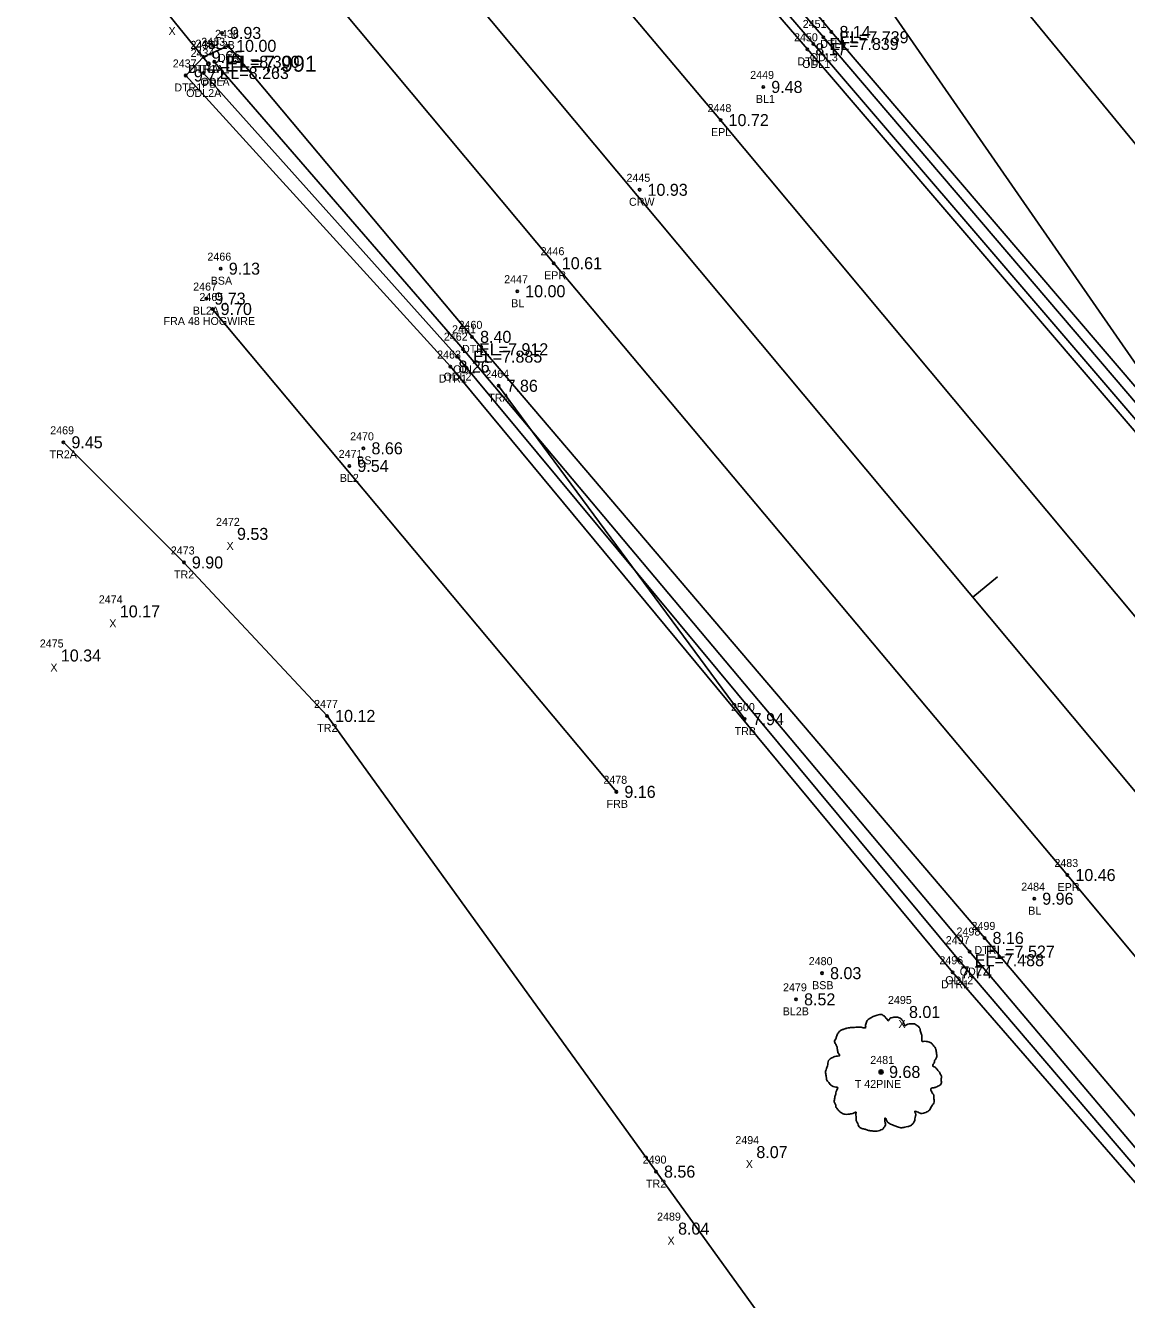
# Model space of a CAD drawing. Extents: x 2042117 to 2045853, y 303080 to 309569.
# Drawn here: x 2044504.4 to 2044642, y 304432.9 to 304592 of the extents above; entities that cross this region are included whole.
import ezdxf

# ---------------------------------------------------------------- set-up
doc = ezdxf.new("R2010")
doc.units = 0
for name, color, linetype in [('RD_DTM_BkLn_txCode', 7, 'Continuous'), ('RD_EX_DR_Pipe', 7, 'Continuous'), ('RD_EX_DR_Pipe_txCode', 7, 'Continuous'), ('RD_EX_Fence_Other', 7, 'Continuous'), ('RD_EX_Fence_Other_txCode', 7, 'Continuous'), ('RD_EX_H2O', 7, 'Continuous'), ('RD_EX_H2O_txCode', 7, 'Continuous'), ('RD_EX_Misc_txCode', 7, 'Continuous'), ('RD_EX_Road', 7, 'Continuous'), ('RD_EX_Road_txCode', 7, 'Continuous'), ('RD_EX_TX_Fence_Other_ELEV', 7, 'Continuous'), ('RD_EX_TX_H2O_ELEV', 7, 'Continuous'), ('RD_EX_TX_Misc_ELEV', 7, 'Continuous'), ('RD_EX_TX_Road_ELEV', 7, 'Continuous'), ('RD_EX_TX_VEG_ELEV', 7, 'Continuous'), ('RD_EX_VEG', 7, 'Continuous'), ('RD_EX_VEG_txCode', 7, 'Continuous'), ('RD_HC_Cl', 7, 'Continuous'), ('RD_HC_Data_Tic', 7, 'Continuous'), ('RD_HC_Survey_ELEV', 7, 'Continuous'), ('RD_HC_Survey_txCode', 7, 'Continuous'), ('RD_SMD_Locator', 7, 'Continuous'), ('RD_TX_Pipe_ElevEX', 7, 'Continuous')]:
    doc.layers.add(name, color=color, linetype=linetype)

msp = doc.modelspace()

# ---------------------------------------------------------------- linework, layer by layer
at = {"layer": 'RD_EX_DR_Pipe'}
msp.add_line((2044518.06, 304598.7), (2044527.29, 304587.27), dxfattribs=at)
at = {"layer": 'RD_EX_Fence_Other'}
msp.add_line((2044527.81, 304556.63), (2044578.26, 304496.32), dxfattribs=at)
msp.add_lwpolyline([(2044487.63, 304762.15), (2044554.33, 304682.4), (2044620.57, 304604.64), (2044681.6, 304530.46), (2044725.33, 304478.72)], dxfattribs=at)
at = {"layer": 'RD_EX_H2O'}
for points in [[(2044415.25, 304826.5), (2044425.66, 304808.25), (2044476.98, 304747.65), (2044539.62, 304670.39), (2044605.13, 304591.24), (2044669.3, 304516.3), (2044710.53, 304469.32), (2044713.85, 304468.76), (2044716.6, 304472.63), (2044721.53, 304481.66), (2044732.23, 304519.55), (2044759.21, 304613.29), (2044789.62, 304712.59), (2044819.6, 304810.16), (2044847.46, 304908.11)], [(2044411.61, 304823.92), (2044423.39, 304807.22), (2044471.39, 304742.74), (2044536.14, 304667.19), (2044602.88, 304589.74), (2044667.18, 304514.78), (2044710.55, 304465.6), (2044713.57, 304459.34), (2044715.66, 304454.88)], [(2044412.68, 304824.61), (2044424.35, 304807.8), (2044474.04, 304744.84), (2044537.22, 304668.23), (2044604.12, 304590.58), (2044668.25, 304515.54), (2044711.53, 304466.18), (2044714.74, 304463.76), (2044717.49, 304460.61)], [(2044410.56, 304822.99), (2044421.91, 304806.08), (2044470.67, 304741.87), (2044535.46, 304666.28), (2044602.12, 304589.07), (2044666.31, 304514.2), (2044707.72, 304463.54), (2044711.05, 304453.94), (2044714.6, 304446.34)], [(2044526.69, 304588.12), (2044529.75, 304589.5), (2044560.23, 304553.15), (2044624.26, 304478.07), (2044679.39, 304412.98), (2044689.21, 304400.4), (2044696.61, 304396.14)], [(2044526.69, 304588.12), (2044524.46, 304585.8), (2044557.52, 304549.44), (2044620.27, 304473.78), (2044676.08, 304409.54), (2044675.89, 304404.78), (2044683.56, 304394.92), (2044688.93, 304389.15), (2044690.58, 304383.03), (2044681.72, 304360.31), (2044669.72, 304323.23)], [(2044526.69, 304586.11), (2044558.35, 304550.68), (2044621.04, 304475.29), (2044676.74, 304410.12), (2044678.19, 304404.53), (2044685.26, 304396.55), (2044691.41, 304390.93)], [(2044528.02, 304587.51), (2044559.1, 304551.6), (2044622.39, 304476.37), (2044677.57, 304411.07), (2044687.25, 304399.14), (2044692.5, 304393.31)]]:
    msp.add_lwpolyline(points, dxfattribs=at)
at = {"layer": 'RD_EX_Road'}
for points in [[(2043522.11, 305820), (2043547.67, 305789.85), (2043610.72, 305713.32), (2043674.95, 305636.32), (2043738.18, 305559.62), (2043802.42, 305482.71), (2043865.72, 305405.84), (2043929.53, 305328.85), (2043994.13, 305253.28), (2044057.4, 305176.5), (2044121.27, 305100.2), (2044185.29, 305023.54), (2044249.56, 304947.28), (2044313.31, 304870.31), (2044377.09, 304793.29), (2044442, 304716.26), (2044505.92, 304639.55), (2044570.44, 304562.35), (2044634.61, 304485.93), (2044698.46, 304409.27), (2044762.46, 304332.37)], [(2044395.5, 304814.18), (2044398.16, 304811.09), (2044461.8, 304734.03), (2044526.04, 304657.6), (2044591.28, 304580.23), (2044655.29, 304503.62), (2044718.26, 304427.32), (2044783.13, 304349.86)]]:
    msp.add_lwpolyline(points, dxfattribs=at)
at = {"layer": 'RD_EX_VEG'}
msp.add_line((2044563.54, 304547.04), (2044594.29, 304505.4), dxfattribs=at)
for points in [[(2044387.58, 304996.88), (2044390.53, 304961.86), (2044388.93, 304944.71), (2044397.82, 304931.38), (2044395.87, 304907.56), (2044407.42, 304883.17), (2044412.64, 304877.39), (2044413.34, 304846.91), (2044417.62, 304826.21), (2044417.53, 304827.99), (2044425.41, 304820.87), (2044430.68, 304811.06), (2044486.4, 304757.95), (2044546.53, 304677.07), (2044611.02, 304596.16), (2044662.5, 304521.9), (2044713.91, 304454.08), (2044725.96, 304441.86), (2044733.75, 304433.55)], [(2044509.17, 304539.98), (2044524.22, 304524.97), (2044542.12, 304505.8), (2044583.21, 304448.88), (2044599.3, 304426.6), (2044609.14, 304424.55), (2044616.83, 304408.81), (2044657.84, 304363.53)]]:
    msp.add_lwpolyline(points, dxfattribs=at)
for centre, radius in [((2044611.33, 304461.33), 0.25), ((2044611.32, 304461.31), 0.0001)]:
    msp.add_circle(centre, radius, dxfattribs=at)
for points in [[(2044611.46, 304468.5), (2044611.16, 304468.52), (2044610.84, 304468.42), (2044610.59, 304468.32), (2044610.36, 304468.25), (2044610.14, 304468.15), (2044609.84, 304467.97), (2044609.61, 304467.77), (2044609.49, 304467.53), (2044609.44, 304467.3), (2044609.39, 304467.03), (2044609.39, 304466.85), (2044609.26, 304466.83), (2044609.11, 304466.85), (2044608.86, 304466.93), (2044608.61, 304466.93), (2044608.36, 304466.93), (2044608.01, 304466.9), (2044607.66, 304466.9), (2044607.39, 304466.85), (2044607.06, 304466.8), (2044606.69, 304466.68), (2044606.34, 304466.55), (2044606.04, 304466.3), (2044605.79, 304465.83), (2044605.66, 304465.48), (2044605.51, 304465.23), (2044605.66, 304464.78), (2044605.84, 304464.43), (2044605.86, 304464.23), (2044605.94, 304463.8), (2044606.04, 304463.58), (2044606.16, 304463.38), (2044606.09, 304463.35), (2044605.71, 304463.3), (2044605.41, 304463.2), (2044604.99, 304462.98), (2044604.77, 304462.75), (2044604.67, 304462.43), (2044604.64, 304462.08), (2044604.54, 304461.88), (2044604.47, 304461.6), (2044604.44, 304461.53), (2044604.39, 304461.2), (2044604.49, 304460.75), (2044604.52, 304460.4), (2044604.64, 304460.18), (2044604.79, 304460), (2044604.96, 304459.75), (2044605.36, 304459.53), (2044605.69, 304459.43), (2044605.89, 304459.4), (2044605.71, 304458.9), (2044605.66, 304458.55), (2044605.54, 304458.15), (2044605.54, 304458.08), (2044605.49, 304457.6), (2044605.64, 304457.28), (2044605.71, 304456.9), (2044605.89, 304456.68), (2044606.16, 304456.38), (2044606.49, 304456.16), (2044606.99, 304456.03), (2044607.39, 304456.06), (2044607.96, 304456.23), (2044608.21, 304456.3), (2044608.19, 304456.13), (2044608.21, 304455.76), (2044608.21, 304455.33), (2044608.36, 304455.01), (2044608.46, 304454.73), (2044608.61, 304454.48), (2044608.94, 304454.26), (2044609.34, 304454.18), (2044609.76, 304454.03), (2044610.21, 304453.96), (2044610.71, 304453.93), (2044611.31, 304454.08), (2044611.59, 304454.21), (2044611.69, 304454.38), (2044611.89, 304454.76), (2044611.84, 304454.98), (2044611.86, 304455.58), (2044611.96, 304455.41), (2044612.14, 304455.06), (2044612.64, 304454.76), (2044613.04, 304454.58), (2044613.51, 304454.43), (2044613.81, 304454.36), (2044614.29, 304454.43), (2044614.66, 304454.51), (2044615.04, 304454.63), (2044615.34, 304454.91), (2044615.51, 304455.18), (2044615.56, 304455.46), (2044615.64, 304455.83), (2044615.69, 304456.01)], [(2044615.69, 304456.01), (2044615.61, 304456.18), (2044615.56, 304456.43), (2044615.64, 304456.4), (2044615.81, 304456.35), (2044616.09, 304456.23), (2044616.31, 304456.16), (2044616.63, 304456.18), (2044616.91, 304456.28), (2044617.36, 304456.55), (2044617.63, 304457.03), (2044617.91, 304457.43), (2044617.98, 304457.75), (2044617.93, 304457.98), (2044617.91, 304458.48), (2044617.71, 304458.73), (2044617.66, 304458.85), (2044617.56, 304459.25), (2044617.63, 304459.3), (2044617.91, 304459.35), (2044618.28, 304459.48), (2044618.56, 304459.6), (2044618.78, 304459.78), (2044618.86, 304460), (2044618.83, 304460.4), (2044618.88, 304460.8), (2044618.81, 304460.95), (2044618.71, 304461.1), (2044618.63, 304461.3), (2044618.48, 304461.45), (2044618.38, 304461.6), (2044618.28, 304461.7), (2044618.16, 304461.85), (2044617.98, 304461.98), (2044617.83, 304462.03), (2044617.78, 304462.18), (2044617.93, 304462.38), (2044617.98, 304462.48), (2044618.01, 304462.7), (2044618.23, 304463.05), (2044618.28, 304463.45), (2044618.23, 304463.88), (2044618.18, 304464.15), (2044618.03, 304464.43), (2044617.83, 304464.68), (2044617.71, 304464.85), (2044617.53, 304464.98), (2044617.21, 304465.1), (2044616.96, 304465.15), (2044616.61, 304465.15), (2044616.41, 304465.2), (2044616.43, 304465.25), (2044616.43, 304465.4), (2044616.43, 304465.68), (2044616.36, 304466.13), (2044616.21, 304466.63), (2044616.21, 304466.65), (2044616.11, 304466.9), (2044615.89, 304467.1), (2044615.71, 304467.2), (2044615.51, 304467.33), (2044615.26, 304467.35), (2044614.96, 304467.35), (2044614.69, 304467.3), (2044614.49, 304467.2), (2044614.31, 304467.08), (2044614.24, 304467.23), (2044614.14, 304467.53), (2044614.09, 304467.67), (2044613.94, 304467.85), (2044613.71, 304468.05), (2044613.26, 304468.17), (2044612.64, 304468.1), (2044612.34, 304467.9), (2044612.19, 304467.72), (2044612.14, 304467.85), (2044611.94, 304468.05), (2044611.84, 304468.22), (2044611.66, 304468.35), (2044611.51, 304468.45), (2044611.41, 304468.5)]]:
    msp.add_spline(points, degree=3, dxfattribs=at)
at = {"layer": 'RD_HC_Cl'}
msp.add_line((2043284.3, 306123.24), (2045221.31, 303804), dxfattribs=at)
at = {"layer": 'RD_HC_Data_Tic'}
msp.add_line((2044622.79, 304520.62), (2044625.86, 304523.18), dxfattribs=at)
at = {"layer": 'RD_SMD_Locator'}
for centre, radius in [((2044528.98, 304591.11), 0.15), ((2044605.13, 304591.24), 0.15), ((2044529.75, 304589.5), 0.15), ((2044602.88, 304589.74), 0.15), ((2044604.12, 304590.58), 0.15), ((2044526.69, 304588.12), 0.15), ((2044526.69, 304588.12), 0.15), ((2044528.02, 304587.51), 0.15), ((2044602.12, 304589.07), 0.15), ((2044526.69, 304586.11), 0.15), ((2044527.29, 304587.27), 0.2), ((2044524.46, 304585.8), 0.15), ((2044596.61, 304584.37), 0.15), ((2044591.28, 304580.23), 0.15), ((2044581.15, 304571.52), 0.15), ((2044570.44, 304562.35), 0.15), ((2044528.83, 304561.67), 0.15), ((2044527.03, 304557.93), 0.15), ((2044565.87, 304558.85), 0.15), ((2044527.81, 304556.63), 0.15), ((2044560.23, 304553.15), 0.15), ((2044559.1, 304551.6), 0.15), ((2044557.52, 304549.44), 0.15), ((2044558.35, 304550.68), 0.15), ((2044563.54, 304547.04), 0.15), ((2044509.17, 304539.98), 0.15), ((2044546.66, 304539.23), 0.15), ((2044544.9, 304537.03), 0.15), ((2044524.22, 304524.97), 0.15), ((2044542.12, 304505.8), 0.15), ((2044594.29, 304505.4), 0.15), ((2044578.26, 304496.32), 0.15), ((2044634.61, 304485.93), 0.15), ((2044630.47, 304482.97), 0.15), ((2044624.26, 304478.07), 0.15), ((2044622.39, 304476.37), 0.15), ((2044621.04, 304475.29), 0.15), ((2044603.96, 304473.67), 0.15), ((2044620.27, 304473.78), 0.15), ((2044600.71, 304470.4), 0.15), ((2044611.33, 304461.33), 0.15), ((2044583.21, 304448.88), 0.15)]:
    msp.add_circle(centre, radius, dxfattribs=at)

# ---------------------------------------------------------------- texts
at = {"layer": 'RD_DTM_BkLn_txCode'}
for s, p in [('BL2B', (2044527.31, 304589.11)), ('2449', (2044594.98, 304585.37)), ('BL1', (2044595.69, 304582.37)), ('2466', (2044527.16, 304562.67)), ('BSA', (2044527.57, 304559.67)), ('2447', (2044564.24, 304559.85)), ('2467', (2044525.38, 304558.93)), ('BL', (2044565.12, 304556.85)), ('BL2A', (2044525.34, 304555.93)), ('2470', (2044544.99, 304540.23)), ('2471', (2044543.56, 304538.03)), ('BS', (2044545.88, 304537.23)), ('BL2', (2044543.7, 304535.03)), ('2484', (2044628.84, 304483.97)), ('BL', (2044629.72, 304480.97)), ('2480', (2044602.29, 304474.67)), ('2479', (2044599.08, 304471.4)), ('BSB', (2044602.71, 304471.67)), ('BL2B', (2044599.04, 304468.4))]:
    msp.add_text(s, height=1, dxfattribs=at).set_placement(p)
at = {"layer": 'RD_EX_DR_Pipe_txCode'}
for s, p in [('2432', (2044525.66, 304589.27)), ('PB', (2044526.51, 304584.27))]:
    msp.add_text(s, height=1, dxfattribs=at).set_placement(p)
at = {"layer": 'RD_EX_Fence_Other_txCode'}
for s, p in [('2465', (2044526.16, 304557.63)), ('FRA 48 HOGWIRE', (2044521.68, 304554.63)), ('2478', (2044576.63, 304497.32)), ('FRB', (2044577.03, 304494.32))]:
    msp.add_text(s, height=1, dxfattribs=at).set_placement(p)
at = {"layer": 'RD_EX_H2O_txCode'}
for s, p in [('2451', (2044601.54, 304591.74)), ('2438', (2044528.12, 304590.5)), ('2450', (2044600.45, 304590.07)), ('2436', (2044525.03, 304589.12)), ('2435', (2044525.06, 304589.12)), ('2433', (2044526.39, 304589.51)), ('DTL1', (2044603.72, 304589.24)), ('2437', (2044522.83, 304586.8)), ('2434', (2044525.06, 304588.11)), ('DTR', (2044528.48, 304587.5)), ('DTL', (2044600.88, 304587.07)), ('ODL1', (2044601.47, 304586.74)), ('ODL3', (2044602.43, 304587.58)), ('DTR1A', (2044524.77, 304586.12)), ('DTRA', (2044524.93, 304586.12)), ('DTR1', (2044523.03, 304583.8)), ('ODLA', (2044526.29, 304584.51)), ('ODL2A', (2044524.51, 304583.11)), ('2461', (2044557.73, 304553.6)), ('2460', (2044558.54, 304554.15)), ('2462', (2044556.7, 304552.68)), ('2463', (2044555.86, 304550.44)), ('DTR', (2044558.97, 304551.15)), ('ODL', (2044557.86, 304548.6)), ('DTR1', (2044556.08, 304547.44)), ('ODL2', (2044556.66, 304547.68)), ('2499', (2044622.63, 304479.07)), ('2497', (2044619.41, 304477.29)), ('2498', (2044620.76, 304478.37)), ('DTR', (2044622.99, 304476.07)), ('2496', (2044618.61, 304474.78)), ('ODL2', (2044619.35, 304472.29)), ('ODL', (2044621.15, 304473.37)), ('DTR1', (2044618.83, 304471.78))]:
    msp.add_text(s, height=1, dxfattribs=at).set_placement(p)
at = {"layer": 'RD_EX_Misc_txCode'}
for s, p in [('X', (2044522.3, 304590.86)), ('2472', (2044528.23, 304529.54)), ('X', (2044529.55, 304526.54)), ('2474', (2044513.59, 304519.86)), ('X', (2044514.9, 304516.86)), ('2475', (2044506.22, 304514.35)), ('X', (2044507.54, 304511.35)), ('2495', (2044612.19, 304469.82)), ('X', (2044613.5, 304466.82)), ('2494', (2044593.12, 304452.32)), ('X', (2044594.43, 304449.32)), ('2489', (2044583.34, 304442.76)), ('X', (2044584.65, 304439.76))]:
    msp.add_text(s, height=1, dxfattribs=at).set_placement(p)
at = {"layer": 'RD_EX_Road_txCode'}
for s, p in [('2448', (2044589.65, 304581.23)), ('EPL', (2044590.08, 304578.23)), ('2446', (2044568.79, 304563.35)), ('EPR', (2044569.22, 304560.35)), ('2483', (2044632.98, 304486.93)), ('EPR', (2044633.38, 304483.93))]:
    msp.add_text(s, height=1, dxfattribs=at).set_placement(p)
at = {"layer": 'RD_EX_TX_Fence_Other_ELEV'}
for s, p in [('9.70', (2044528.81, 304555.88)), ('9.16', (2044579.26, 304495.57))]:
    msp.add_text(s, height=1.5, dxfattribs=at).set_placement(p)
at = {"layer": 'RD_EX_TX_H2O_ELEV'}
for s, p in [('8.14', (2044606.13, 304590.49)), ('EL=7.739', (2044606.12, 304589.83)), ('10.00', (2044530.75, 304588.75)), ('8.17', (2044603.12, 304588.32)), ('EL=7.839', (2044604.88, 304588.99)), ('9.65', (2044527.69, 304587.37)), ('9.65', (2044527.69, 304587.37)), ('EL=8.300', (2044530.02, 304586.76)), ('9.72', (2044525.46, 304585.05)), ('EL=8.263', (2044528.69, 304585.36)), ('8.40', (2044561.23, 304552.4)), ('EL=7.885', (2044560.35, 304549.93)), ('EL=7.912', (2044561.1, 304550.85)), ('8.26', (2044558.52, 304548.69)), ('8.16', (2044625.26, 304477.32)), ('EL=7.527', (2044624.39, 304475.62)), ('EL=7.488', (2044623.04, 304474.54)), ('7.74', (2044621.27, 304473.03))]:
    msp.add_text(s, height=1.5, dxfattribs=at).set_placement(p)
at = {"layer": 'RD_EX_TX_Misc_ELEV'}
for s, p in [('9.93', (2044529.98, 304590.36)), ('9.48', (2044597.61, 304583.62)), ('9.13', (2044529.83, 304560.92)), ('10.00', (2044566.87, 304558.1)), ('9.73', (2044528.03, 304557.18)), ('8.66', (2044547.66, 304538.48)), ('9.54', (2044545.9, 304536.28)), ('9.53', (2044530.86, 304527.79)), ('10.17', (2044516.22, 304518.11)), ('10.34', (2044508.85, 304512.6)), ('9.96', (2044631.47, 304482.22)), ('8.03', (2044604.96, 304472.92)), ('8.52', (2044601.71, 304469.65)), ('8.01', (2044614.82, 304468.07)), ('8.07', (2044595.75, 304450.57)), ('8.04', (2044585.97, 304441.01))]:
    msp.add_text(s, height=1.5, dxfattribs=at).set_placement(p)
at = {"layer": 'RD_EX_TX_Road_ELEV'}
for s, p in [('10.72', (2044592.28, 304579.48)), ('10.61', (2044571.44, 304561.6)), ('10.46', (2044635.61, 304485.18))]:
    msp.add_text(s, height=1.5, dxfattribs=at).set_placement(p)
at = {"layer": 'RD_EX_TX_VEG_ELEV'}
for s, p in [('7.86', (2044564.54, 304546.29)), ('9.45', (2044510.17, 304539.23)), ('9.90', (2044525.22, 304524.22)), ('10.12', (2044543.12, 304505.05)), ('7.94', (2044595.29, 304504.65)), ('9.68', (2044612.33, 304460.58)), ('8.56', (2044584.21, 304448.13))]:
    msp.add_text(s, height=1.5, dxfattribs=at).set_placement(p)
at = {"layer": 'RD_EX_VEG_txCode'}
for s, p in [('2464', (2044561.88, 304548.04)), ('TRA', (2044562.25, 304545.04)), ('2469', (2044507.52, 304540.98)), ('TR2A', (2044507.44, 304537.98)), ('2473', (2044522.59, 304525.97)), ('TR2', (2044522.98, 304522.97)), ('2477', (2044540.49, 304506.8)), ('2500', (2044592.58, 304506.4)), ('TR2', (2044540.88, 304503.8)), ('TRB', (2044593.03, 304503.4)), ('2481', (2044609.98, 304462.33)), ('T 42PINE', (2044608.04, 304459.33)), ('2490', (2044581.54, 304449.88)), ('TR2', (2044581.96, 304446.88))]:
    msp.add_text(s, height=1, dxfattribs=at).set_placement(p)
at = {"layer": 'RD_HC_Survey_ELEV'}
msp.add_text('10.93', height=1.5, dxfattribs=at).set_placement((2044582.15, 304570.77))
at = {"layer": 'RD_HC_Survey_txCode'}
for s, p in [('2445', (2044579.52, 304572.52)), ('CRW', (2044579.83, 304569.52))]:
    msp.add_text(s, height=1, dxfattribs=at).set_placement(p)
at = {"layer": 'RD_TX_Pipe_ElevEX'}
msp.add_text('EL=7.991', height=2, dxfattribs=at).set_placement((2044529.29, 304586.27))

doc.saveas('drawing.dxf')
